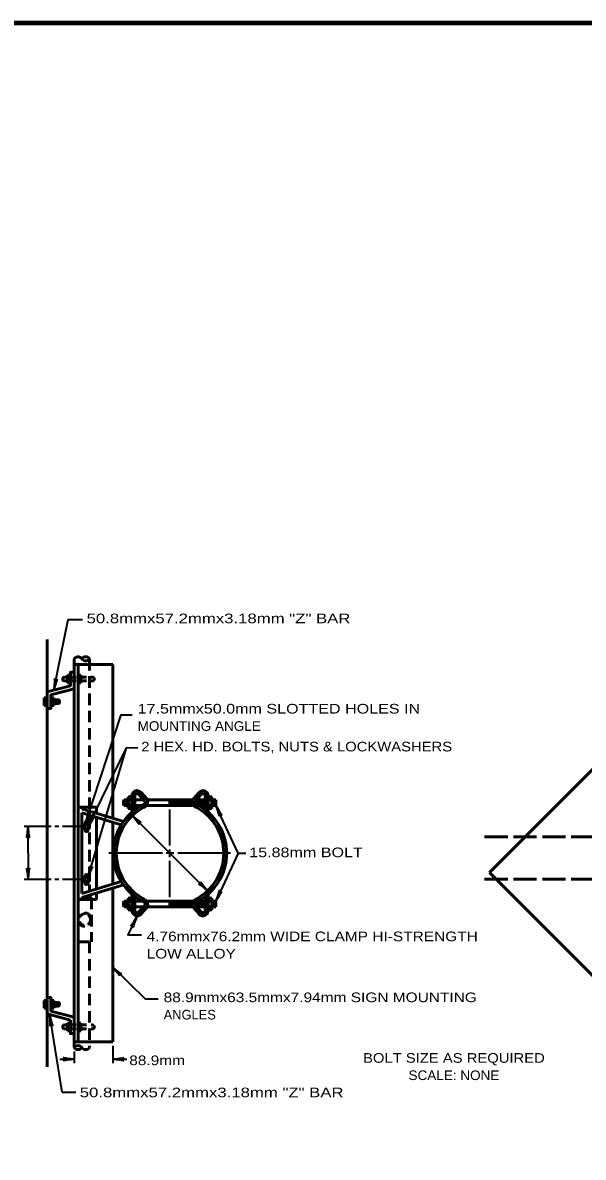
# Model space of a CAD drawing. Extents: x -31 to 825, y 0 to 544.
# Drawn here: x 329.4 to 504.2, y 184.2 to 537.9 of the extents above; entities that cross this region are included whole.
import ezdxf
from ezdxf.enums import TextEntityAlignment as Align

# ---------------------------------------------------------------- set-up
doc = ezdxf.new("R2010")
doc.units = 0
doc.header["$LTSCALE"] = 1.2
for name, pattern in [('LONG_DASHED', [7.5, 6, -1.5]), ('MEDIUM_DASHED', [4.5, 3, -1.5]), ('SHORT_DASHED', [2.7, 1.5, -1.2])]:
    doc.linetypes.add(name, pattern=pattern)
doc.layers.add('1', color=7, linetype='Continuous', lineweight=53)

msp = doc.modelspace()

# ---------------------------------------------------------------- linework, layer by layer
at = {"layer": '1'}
for p, q in [((556.491, 354.616), (474.891, 273.016)), ((337.053, 345.616), (337.053, 212.416)), ((345.453, 339.616), (345.453, 218.416)), ((345.453, 337.816), (357.453, 337.816)), ((346.653, 337.816), (346.653, 220.216)), ((357.453, 337.816), (357.453, 289.936)), ((342.453, 333.916), (344.253, 333.916)), ((342.453, 332.716), (344.253, 332.716)), ((343.353, 334.516), (343.353, 332.116)), ((343.353, 334.516), (344.253, 334.516)), ((346.653, 334.516), (347.553, 334.516)), ((347.553, 334.516), (347.553, 332.116)), ((343.353, 332.116), (344.253, 332.116)), ((346.653, 332.116), (347.553, 332.116)), ((336.134, 327.455), (336.134, 325.055)), ((336.134, 327.455), (337.053, 327.455)), ((336.134, 326.855), (337.053, 326.855)), ((337.053, 325.655), (336.134, 325.655)), ((338.212, 327.455), (339.112, 327.455)), ((338.212, 326.855), (340.312, 326.855)), ((340.312, 325.655), (338.212, 325.655)), ((339.112, 327.455), (339.112, 325.055)), ((339.412, 326.555), (339.412, 325.955)), ((339.712, 326.855), (339.712, 325.655)), ((340.012, 326.555), (340.012, 325.955)), ((340.312, 326.855), (340.312, 325.655)), ((337.053, 325.055), (336.134, 325.055)), ((339.112, 325.055), (338.212, 325.055)), ((365.62, 297.345), (367.49, 295.278)), ((366.288, 297.949), (368.158, 295.882)), ((384.356, 297.949), (382.486, 295.882)), ((385.023, 297.345), (383.153, 295.278)), ((361.053, 295.687), (362.253, 295.687)), ((361.053, 295.687), (361.053, 293.887)), ((361.053, 293.887), (362.253, 293.887)), ((361.353, 295.387), (361.353, 294.187)), ((361.653, 295.687), (361.653, 293.887)), ((361.953, 295.387), (361.953, 294.187)), ((362.253, 296.587), (363.453, 296.587)), ((362.253, 296.587), (362.253, 292.987)), ((362.253, 296.587), (362.553, 295.687)), ((362.253, 294.787), (362.553, 295.687)), ((362.253, 294.787), (362.553, 293.887)), ((362.253, 292.987), (362.553, 293.887)), ((362.553, 295.687), (363.453, 295.687)), ((362.553, 293.887), (363.453, 293.887)), ((363.453, 296.587), (363.453, 291.787)), ((364.353, 296.587), (364.353, 292.518)), ((364.353, 295.687), (367.12, 295.687)), ((364.353, 293.887), (366.475, 293.887)), ((367.955, 293.887), (382.689, 293.887)), ((368.243, 295.687), (382.401, 295.687)), ((375.303, 293.887), (375.303, 295.687)), ((375.903, 294.187), (375.903, 295.387)), ((376.503, 293.887), (376.503, 295.687)), ((377.103, 294.187), (377.103, 295.387)), ((377.703, 293.887), (377.703, 295.687)), ((378.303, 294.187), (378.303, 295.387)), ((378.903, 293.887), (378.903, 295.687)), ((379.503, 294.187), (379.503, 295.387)), ((380.103, 293.887), (380.103, 295.687)), ((380.703, 294.187), (380.703, 295.387)), ((381.303, 293.887), (381.303, 295.687)), ((381.903, 294.187), (381.903, 295.387)), ((383.524, 295.687), (386.291, 295.687)), ((383.703, 294.131), (383.703, 295.687)), ((384.168, 293.887), (386.291, 293.887)), ((384.303, 294.187), (384.303, 295.387)), ((384.903, 293.887), (384.903, 295.687)), ((385.503, 294.187), (385.503, 295.387)), ((386.103, 293.887), (386.103, 295.687)), ((386.291, 296.587), (386.291, 292.518)), ((387.191, 296.587), (387.191, 291.787)), ((387.191, 296.587), (388.391, 296.587)), ((387.191, 295.687), (389.591, 295.687)), ((387.191, 293.887), (389.591, 293.887)), ((388.391, 296.587), (388.391, 292.987)), ((388.691, 295.387), (388.691, 294.187)), ((388.991, 295.687), (388.991, 293.887)), ((389.291, 295.387), (389.291, 294.187)), ((389.591, 295.687), (389.591, 293.887)), ((352.353, 293.416), (346.653, 293.416)), ((347.853, 293.416), (347.853, 292.871)), ((347.853, 292.871), (360.827, 288.904)), ((347.853, 291.616), (360.091, 287.874)), ((347.853, 291.616), (347.853, 266.467)), ((352.353, 293.416), (352.353, 291.495)), ((352.353, 290.24), (352.353, 267.843)), ((362.253, 292.987), (363.453, 292.987)), ((387.191, 292.987), (388.391, 292.987)), ((348.344, 287.874), (348.344, 286.674)), ((348.825, 288.113), (348.825, 288.413)), ((349.725, 288.113), (349.725, 288.413)), ((350.207, 287.874), (350.207, 286.674)), ((357.453, 288.681), (357.453, 269.402)), ((348.825, 286.435), (348.825, 286.135)), ((349.725, 286.435), (349.725, 286.135)), ((347.853, 266.467), (360.091, 270.209)), ((347.853, 265.213), (360.827, 269.179)), ((348.344, 270.194), (348.344, 271.394)), ((348.825, 271.634), (348.825, 271.934)), ((348.825, 269.955), (348.825, 269.655)), ((349.725, 271.634), (349.725, 271.934)), ((349.725, 269.955), (349.725, 269.655)), ((350.207, 270.194), (350.207, 271.394)), ((352.353, 266.588), (352.353, 264.616)), ((357.453, 268.148), (357.453, 220.216)), ((363.453, 261.451), (363.453, 266.251)), ((364.353, 261.451), (364.353, 265.52)), ((386.291, 261.451), (386.291, 265.52)), ((387.191, 261.451), (387.191, 266.251)), ((352.353, 264.616), (346.653, 264.616)), ((347.853, 265.213), (347.853, 264.616)), ((361.053, 264.111), (362.253, 264.111)), ((361.053, 262.311), (361.053, 264.111)), ((361.053, 262.311), (362.253, 262.311)), ((361.353, 262.611), (361.353, 263.811)), ((361.653, 262.311), (361.653, 264.111)), ((361.953, 262.611), (361.953, 263.811)), ((362.253, 265.011), (363.453, 265.011)), ((362.253, 261.411), (362.253, 265.011)), ((362.253, 265.011), (362.553, 264.111)), ((362.253, 263.211), (362.553, 264.111)), ((362.253, 263.211), (362.553, 262.311)), ((362.253, 261.411), (362.553, 262.311)), ((362.553, 264.111), (363.453, 264.111)), ((362.553, 262.311), (363.453, 262.311)), ((364.353, 264.111), (366.475, 264.111)), ((364.353, 262.311), (367.12, 262.311)), ((365.62, 260.693), (367.49, 262.76)), ((366.288, 260.089), (368.158, 262.156)), ((367.955, 264.111), (382.689, 264.111)), ((368.243, 262.311), (382.401, 262.311)), ((375.303, 264.111), (375.303, 262.311)), ((375.903, 263.811), (375.903, 262.611)), ((376.503, 264.111), (376.503, 262.311)), ((377.103, 263.811), (377.103, 262.611)), ((377.703, 264.111), (377.703, 262.311)), ((378.303, 263.811), (378.303, 262.611)), ((378.903, 264.111), (378.903, 262.311)), ((379.503, 263.811), (379.503, 262.611)), ((380.103, 264.111), (380.103, 262.311)), ((380.703, 263.811), (380.703, 262.611)), ((381.303, 264.111), (381.303, 262.311)), ((381.903, 263.811), (381.903, 262.611)), ((384.356, 260.089), (382.486, 262.156)), ((385.023, 260.693), (383.153, 262.76)), ((383.524, 262.311), (386.291, 262.311)), ((383.703, 263.867), (383.703, 262.311)), ((384.168, 264.111), (386.291, 264.111)), ((384.303, 263.811), (384.303, 262.611)), ((384.903, 264.111), (384.903, 262.311)), ((385.503, 263.811), (385.503, 262.611)), ((386.103, 264.111), (386.103, 262.311)), ((387.191, 265.011), (388.391, 265.011)), ((387.191, 264.111), (389.591, 264.111)), ((387.191, 262.311), (389.591, 262.311)), ((388.391, 261.411), (388.391, 265.011)), ((388.691, 262.611), (388.691, 263.811)), ((388.991, 262.311), (388.991, 264.111)), ((389.291, 262.611), (389.291, 263.811)), ((389.591, 262.311), (389.591, 264.111)), ((362.253, 261.411), (363.453, 261.411)), ((387.191, 261.411), (388.391, 261.411)), ((336.134, 230.73), (336.134, 233.13)), ((337.053, 233.13), (336.134, 233.13)), ((337.053, 232.53), (336.134, 232.53)), ((336.134, 231.33), (337.053, 231.33)), ((336.134, 230.73), (337.053, 230.73)), ((339.112, 233.13), (338.212, 233.13)), ((340.312, 232.53), (338.212, 232.53)), ((338.212, 231.33), (340.312, 231.33)), ((338.212, 230.73), (339.112, 230.73)), ((339.112, 230.73), (339.112, 233.13)), ((339.412, 231.63), (339.412, 232.23)), ((339.712, 231.33), (339.712, 232.53)), ((340.012, 231.63), (340.012, 232.23)), ((340.312, 231.33), (340.312, 232.53)), ((344.253, 226.969), (337.053, 228.898)), ((342.453, 225.469), (344.253, 225.469)), ((342.453, 224.269), (344.253, 224.269)), ((343.353, 223.669), (343.353, 226.069)), ((343.353, 226.069), (344.253, 226.069)), ((343.353, 223.669), (344.253, 223.669)), ((346.653, 226.069), (347.553, 226.069)), ((346.653, 223.669), (347.553, 223.669)), ((347.553, 223.669), (347.553, 226.069)), ((345.453, 220.216), (357.453, 220.216))]:
    msp.add_line(p, q, dxfattribs=at)
at = {"layer": '1', "linetype": 'MEDIUM_DASHED'}
for p, q in [((350.253, 339.616), (350.253, 292.137)), ((350.253, 290.882), (350.253, 267.201)), ((350.253, 265.946), (350.253, 265.213)), ((347.853, 265.213), (350.853, 265.213)), ((350.853, 265.213), (350.853, 251.413)), ((346.653, 251.413), (350.853, 251.413)), ((350.253, 251.413), (350.253, 218.416))]:
    msp.add_line(p, q, dxfattribs=at)
at = {"layer": '1', "linetype": 'SHORT_DASHED'}
for p, q in [((344.253, 333.916), (351.153, 333.916)), ((344.253, 332.716), (351.153, 332.716)), ((344.253, 225.469), (351.153, 225.469)), ((344.253, 224.269), (351.153, 224.269))]:
    msp.add_line(p, q, dxfattribs=at)
at = {"layer": '1', "lineweight": 35}
for p, q in [((350.048, 287.777), (361.738, 311.9)), ((396.593, 279.016), (389.591, 293.887)), ((387.025, 267.29), (363.568, 290.747)), ((375.303, 281.399), (375.303, 292.687)), ((338.253, 287.316), (329.849, 287.316)), ((331.049, 287.316), (331.084, 270.866)), ((340.653, 287.316), (339.453, 287.316)), ((348.149, 287.316), (341.853, 287.316)), ((375.303, 277.799), (375.303, 280.199)), ((372.93, 279.016), (356.253, 279.016)), ((376.53, 279.016), (374.13, 279.016)), ((375.303, 265.311), (375.303, 276.599)), ((394.193, 279.016), (377.73, 279.016)), ((396.593, 279.016), (389.591, 264.111)), ((396.593, 279.016), (398.993, 279.016)), ((338.253, 270.866), (329.884, 270.866)), ((340.653, 270.866), (339.453, 270.866)), ((348.184, 270.866), (341.853, 270.866)), ((341.679, 204.517), (337.834, 228.576)), ((345.453, 217.216), (345.453, 213.616)), ((357.453, 219.016), (357.453, 213.616)), ((341.004, 214.816), (345.453, 214.816)), ((357.453, 214.816), (361.847, 214.816)), ((341.679, 204.517), (345.928, 204.517))]:
    msp.add_line(p, q, dxfattribs=at)
at = {"layer": '1', "linetype": 'LONG_DASHED'}
for p, q in [((473.391, 284.116), (532.791, 284.116)), ((473.391, 270.916), (532.791, 270.916))]:
    msp.add_line(p, q, dxfattribs=at)
at = {"layer": '1', "lineweight": 158}
msp.add_lwpolyline([(818.018, 537.903), (26.318, 537.803), (26.418, 11.803)], dxfattribs=at)
at = {"layer": '1', "lineweight": 35}
for points in [[(339.118, 329.97), (343.524, 351.854), (348.085, 351.854)], [(349.166, 288.954), (360.121, 322.197), (363.502, 322.197)], [(349.804, 271.603), (361.738, 311.9), (365.288, 311.931)], [(364.947, 259.185), (362.218, 253.589), (366.448, 253.589)], [(357.444, 243.49), (367.539, 233.664), (371.627, 233.664)]]:
    msp.add_lwpolyline(points, dxfattribs=at)
at = {"layer": '1'}
for points in [[(345.453, 335.416), (344.253, 335.416), (344.253, 331.216), (337.053, 329.287)], [(345.453, 330.295), (338.212, 328.355), (338.212, 324.155), (337.012, 324.155)], [(348.344, 287.874), (349.276, 288.34), (350.207, 287.874)], [(350.207, 286.674), (349.276, 286.208), (348.344, 286.674)], [(474.891, 273.016), (558.891, 189.016), (642.891, 273.016)], [(350.207, 271.394), (349.276, 271.86), (348.344, 271.394)], [(348.344, 270.194), (349.276, 269.728), (350.207, 270.194)], [(345.453, 227.89), (338.212, 229.83), (338.212, 234.03), (337.012, 234.03)], [(345.453, 222.769), (344.253, 222.769), (344.253, 226.969)]]:
    msp.add_lwpolyline(points, dxfattribs=at)
for centre in [(349.267, 287.286), (349.267, 270.783)]:
    msp.add_circle(centre, 0.6, dxfattribs=at)
at = {"layer": '1', "linetype": 'SHORT_DASHED'}
for centre, radius in [((348.743, 258.306), 2.072), ((348.75, 258.314), 1.8)]:
    msp.add_circle(centre, radius, dxfattribs=at)
at = {"layer": '1'}
for centre, radius, start, end in [((346.653, 338.768), 1.47, 35.26037, 144.73963), ((349.053, 338.777), 1.47, 35.26037, 144.73963), ((349.053, 340.464), 1.47, 215.26037, 324.73963), ((342.471, 333.316), 0.6, 91.72609, 268.27391), ((340.294, 326.255), 0.6, 271.72609, 88.27391), ((365.04, 296.915), 1.621, 39.66926, 191.65422), ((365.058, 296.847), 0.751, 41.54924, 200.22923), ((385.603, 296.915), 1.621, 348.34578, 140.33074), ((385.586, 296.847), 0.751, 339.77077, 138.45076), ((374.549, 279.042), 16.899, 116.59402, 243.48449), ((362.53, 294.787), 1.73, 148.65416, 211.34584), ((366.508, 295.042), 1.851, 284.90211, 26.9838), ((366.868, 294.882), 0.738, 279.08676, 32.47512), ((384.135, 295.042), 1.851, 153.0162, 255.09789), ((383.776, 294.882), 0.738, 147.52488, 260.91324), ((376.094, 279.042), 16.899, 296.51551, 63.40598), ((374.781, 279.042), 16.209, 118.75187, 241.33156), ((375.862, 279.042), 16.209, 298.66844, 61.24813), ((349.275, 288.372), 0.452, 5.18502, 174.81498), ((349.275, 286.176), 0.452, 185.18502, 354.81498), ((349.275, 271.893), 0.452, 5.18502, 174.81498), ((349.275, 269.696), 0.452, 185.18502, 354.81498), ((362.53, 263.211), 1.73, 148.65416, 211.34584), ((366.508, 262.996), 1.851, 333.0162, 75.09789), ((366.868, 263.156), 0.738, 327.52488, 80.91324), ((384.135, 262.996), 1.851, 104.90211, 206.9838), ((383.776, 263.156), 0.738, 99.08676, 212.47512), ((365.04, 261.123), 1.621, 168.34578, 320.33074), ((365.058, 261.191), 0.751, 159.77077, 318.45076), ((385.603, 261.123), 1.621, 219.66926, 11.65422), ((385.586, 261.191), 0.751, 221.54924, 20.22923), ((340.294, 231.93), 0.6, 271.72609, 88.27391), ((342.471, 224.869), 0.6, 91.72609, 268.27391), ((346.653, 217.568), 1.47, 35.26037, 144.73963), ((346.653, 219.255), 1.47, 215.26037, 324.73963), ((349.053, 219.264), 1.47, 215.26037, 324.73963)]:
    msp.add_arc(centre, radius, start, end, dxfattribs=at)
at = {"layer": '1', "linetype": 'SHORT_DASHED'}
for centre in [(351.135, 333.316), (351.135, 224.869)]:
    msp.add_arc(centre, 0.6, 271.72609, 88.27391, dxfattribs=at)
at = {"layer": '1', "lineweight": 40}
for centre, major_axis, ratio, start_param, end_param in [((339.052, 331.32), (-0.239, -2.138), 0.122415, 0.8963533, 3.1415927), ((339.632, 331.238), (0.623, 2.025), 0.07063, 6.2823074, 8.5597026), ((389.934, 292.562), (-0.707, 1.997), 0.07063, 3.1407148, 5.41811), ((389.934, 292.562), (-0.707, 1.997), 0.07063, 3.1407148, 5.41811), ((390.449, 292.844), (-1.082, 1.859), 0.122415, 0.8963533, 3.1415927), ((390.449, 292.844), (-1.082, 1.859), 0.122415, 0.8963533, 3.1415927), ((349.261, 290.302), (-0.493, -2.094), 0.122415, 0.8963533, 3.1415927), ((349.261, 290.302), (-0.493, -2.094), 0.122415, 0.8963533, 3.1415927), ((349.828, 290.152), (0.86, 1.936), 0.07063, 6.2823074, 8.5597026), ((349.828, 290.152), (0.86, 1.936), 0.07063, 6.2823074, 8.5597026), ((350.321, 289.1), (-0.766, -2.01), 0.122415, 0.8963533, 3.1415927), ((350.321, 289.1), (-0.766, -2.01), 0.122415, 0.8963533, 3.1415927), ((350.863, 288.877), (1.109, 1.805), 0.07063, 6.2823074, 8.5597026), ((350.863, 288.877), (1.109, 1.805), 0.07063, 6.2823074, 8.5597026), ((364.339, 289.617), (1.341, -1.639), 0.07063, 6.2823074, 8.5597026), ((364.728, 290.055), (-1.648, 1.383), 0.122415, 0.8963533, 3.1415927), ((330.798, 285.971), (-0.206, -2.108), 0.07063, 6.2823074, 8.5597026), ((331.383, 286.008), (-0.192, 2.142), 0.122415, 0.8963533, 3.1415927), ((330.749, 272.175), (0.192, -2.142), 0.122415, 0.8963533, 3.1415927), ((331.335, 272.212), (0.206, 2.108), 0.07063, 6.2823074, 8.5597026), ((349.857, 272.953), (-0.429, -2.108), 0.122415, 0.8963533, 3.1415927), ((350.429, 272.821), (0.801, 1.961), 0.07063, 6.2823074, 8.5597026), ((385.865, 267.981), (1.648, -1.383), 0.122415, 0.8963533, 3.1415927), ((386.254, 268.42), (-1.341, 1.639), 0.07063, 6.2823074, 8.5597026), ((389.848, 265.437), (-0.742, -2.019), 0.122415, 0.8963533, 3.1415927), ((390.392, 265.22), (1.087, 1.818), 0.07063, 6.2823074, 8.5597026), ((364.129, 258.087), (-1.113, -1.802), 0.07063, 6.2823074, 8.5597026), ((364.671, 257.862), (0.771, 2.008), 0.122415, 0.8963533, 3.1415927), ((358.23, 242.371), (-1.363, 1.621), 0.07063, 3.1407148, 5.41811), ((358.613, 242.815), (-1.666, 1.36), 0.122415, 0.8963533, 3.1415927), ((337.795, 227.208), (-0.124, 2.115), 0.07063, 3.1407148, 5.41811), ((338.368, 227.335), (-0.523, 2.086), 0.122415, 0.8963533, 3.1415927), ((344.143, 214.484), (2.143, 0.187), 0.122415, 0.8963533, 3.1415927), ((344.108, 215.07), (2.108, -0.211), 0.07063, 3.1407148, 5.41811), ((358.797, 214.562), (-2.108, 0.211), 0.07063, 3.1407148, 5.41811), ((358.762, 215.148), (-2.143, -0.187), 0.122415, 0.8963533, 3.1415927)]:
    msp.add_ellipse(centre, major_axis=major_axis, ratio=ratio, start_param=start_param, end_param=end_param, dxfattribs=at)

# ---------------------------------------------------------------- texts
at = {"layer": '1'}
for s, width, p in [('50.8mmx57.2mmx3.18mm "Z" BAR', 1.3, (349.315, 350.706)), ('17.5mmx50.0mm SLOTTED HOLES IN', 1.25, (365.236, 322.56)), ('MOUNTING ANGLE', 1.05, (365.236, 317.16)), ('2 HEX. HD. BOLTS, NUTS & LOCKWASHERS', 1.15, (366.353, 310.751)), ('15.88mm BOLT', 1.25, (400.024, 277.782)), ('4.76mmx76.2mm WIDE CLAMP HI-STRENGTH', 1.2, (368.029, 251.591)), ('LOW ALLOY', 1.2, (368.029, 246.191)), ('88.9mmx63.5mmx7.94mm SIGN MOUNTING', 1.2, (373.336, 232.592)), ('88.9mm', 1.2, (362.604, 212.96)), ('50.8mmx57.2mmx3.18mm "Z" BAR', 1.3, (347.184, 202.944))]:
    msp.add_text(s, height=3, dxfattribs=dict(at, width=width)).set_placement(p)
msp.add_text('ANGLES', height=3, dxfattribs=at).set_placement((373.336, 227.192))
for s, width, p in [('BOLT SIZE AS REQUIRED', 1.15, (463.828, 213.701)), ('SCALE: NONE', 1.05, (463.828, 208.301))]:
    msp.add_text(s, height=3, dxfattribs=dict(at, width=width)).set_placement(p, align=Align.CENTER)

doc.saveas('drawing.dxf')
